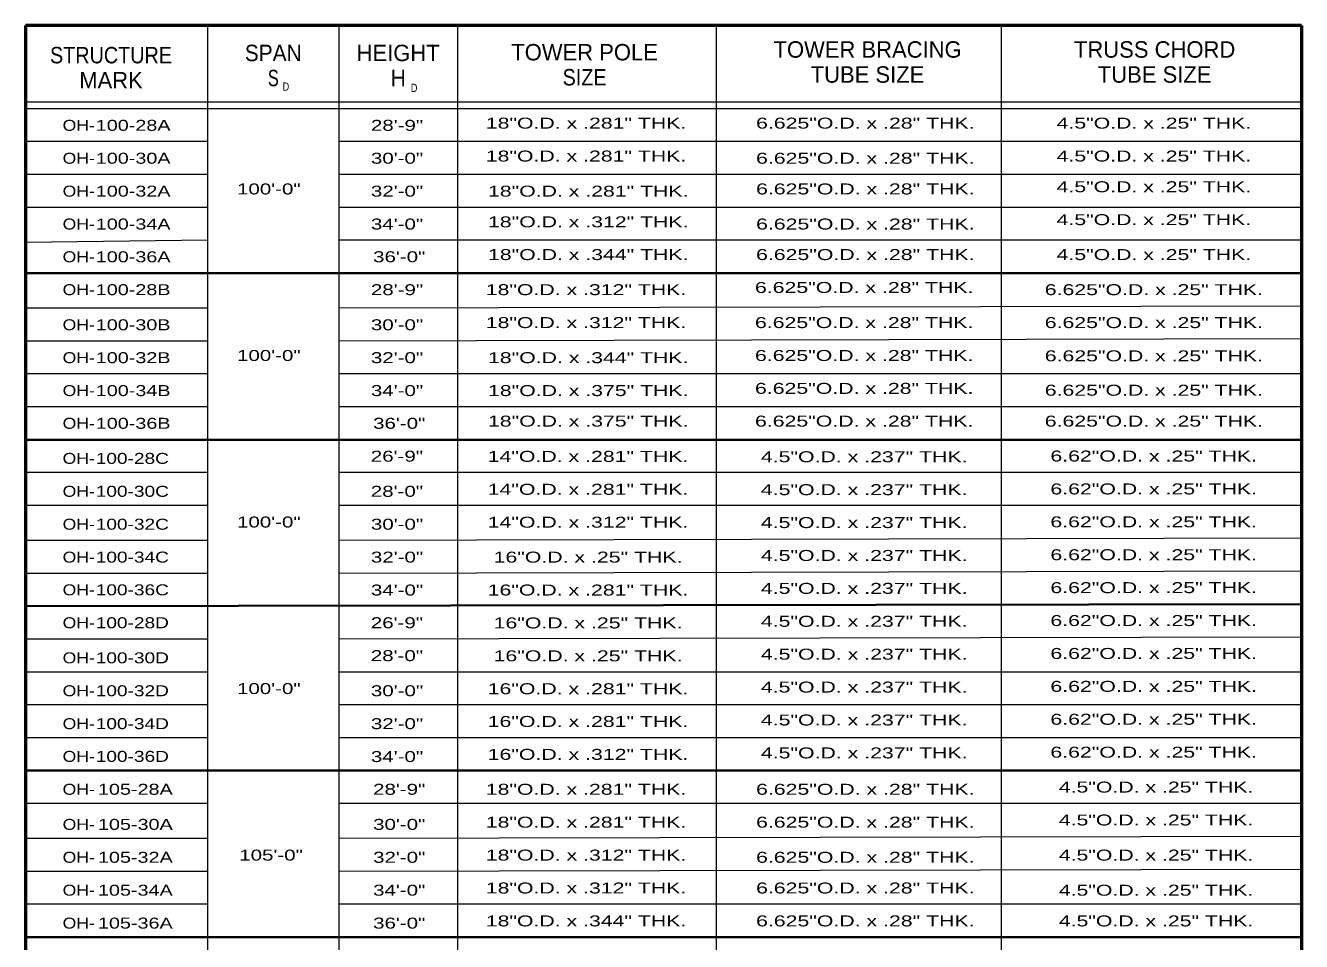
# Model space of a CAD drawing. Extents: x -34822.8 to -34815.8, y -181502.4 to -181492.3.
# Drawn here: x -34822.76 to -34815.78, y -181497.35 to -181492.34 of the extents above; entities that cross this region are included whole.
import ezdxf
from ezdxf.enums import TextEntityAlignment as Align

# ---------------------------------------------------------------- set-up
doc = ezdxf.new("R2010")
doc.units = 0
doc.header["$LTSCALE"] = 0.024
doc.layers.add('1', color=7, linetype='Continuous', lineweight=13)
doc.layers.add('13', color=7, linetype='Continuous')

msp = doc.modelspace()

# ---------------------------------------------------------------- linework, layer by layer
at = {"layer": '1', "lineweight": 53}
for p, q in [((-34815.779, -181492.336), (-34822.756, -181492.336)), ((-34822.756, -181492.336), (-34822.756, -181500.045)), ((-34815.779, -181492.336), (-34815.779, -181500.033))]:
    msp.add_line(p, q, dxfattribs=at)
at = {"layer": '1'}
for p, q in [((-34821.761, -181492.336), (-34821.761, -181500.045)), ((-34821.042, -181492.336), (-34821.042, -181500.045)), ((-34820.394, -181492.336), (-34820.394, -181500.045)), ((-34818.98, -181492.336), (-34818.98, -181500.045)), ((-34817.421, -181492.336), (-34817.421, -181500.045)), ((-34815.779, -181492.756), (-34822.756, -181492.756)), ((-34815.779, -181492.792), (-34822.756, -181492.792)), ((-34821.761, -181492.971), (-34822.756, -181492.971)), ((-34815.779, -181492.971), (-34821.042, -181492.971)), ((-34821.761, -181493.151), (-34822.756, -181493.151)), ((-34815.779, -181493.151), (-34821.042, -181493.151)), ((-34821.761, -181493.331), (-34822.756, -181493.331)), ((-34815.779, -181493.331), (-34821.042, -181493.331)), ((-34821.761, -181493.511), (-34822.756, -181493.523)), ((-34815.779, -181493.511), (-34821.042, -181493.511)), ((-34821.761, -181493.883), (-34822.756, -181493.883)), ((-34815.779, -181493.871), (-34821.042, -181493.883)), ((-34821.761, -181494.062), (-34822.756, -181494.062)), ((-34815.779, -181494.05), (-34821.042, -181494.062)), ((-34821.761, -181494.242), (-34822.756, -181494.242)), ((-34815.779, -181494.242), (-34821.042, -181494.242)), ((-34821.761, -181494.422), (-34822.756, -181494.422)), ((-34815.779, -181494.422), (-34821.042, -181494.422)), ((-34821.761, -181494.782), (-34822.756, -181494.782)), ((-34815.779, -181494.782), (-34821.042, -181494.782)), ((-34821.761, -181494.962), (-34822.756, -181494.962)), ((-34815.779, -181494.962), (-34821.042, -181494.962)), ((-34815.779, -181495.141), (-34821.042, -181495.153)), ((-34821.761, -181495.153), (-34822.756, -181495.153)), ((-34821.761, -181495.333), (-34822.756, -181495.333)), ((-34815.779, -181495.321), (-34821.042, -181495.333)), ((-34821.761, -181495.693), (-34822.756, -181495.693)), ((-34815.779, -181495.681), (-34821.042, -181495.693)), ((-34821.761, -181495.873), (-34822.756, -181495.873)), ((-34815.779, -181495.873), (-34821.042, -181495.873)), ((-34821.761, -181496.052), (-34822.756, -181496.052)), ((-34815.779, -181496.052), (-34821.042, -181496.052)), ((-34821.761, -181496.232), (-34822.756, -181496.232)), ((-34815.779, -181496.232), (-34821.042, -181496.232)), ((-34821.761, -181496.592), (-34822.756, -181496.592)), ((-34815.779, -181496.592), (-34821.042, -181496.592)), ((-34821.761, -181496.784), (-34822.756, -181496.784)), ((-34815.779, -181496.772), (-34821.042, -181496.784)), ((-34815.779, -181496.952), (-34821.042, -181496.964)), ((-34821.761, -181496.964), (-34822.756, -181496.964)), ((-34821.761, -181497.143), (-34822.756, -181497.143)), ((-34815.779, -181497.143), (-34821.042, -181497.143))]:
    msp.add_line(p, q, dxfattribs=at)
at = {"layer": '1', "lineweight": 35}
for p, q in [((-34815.779, -181493.691), (-34822.756, -181493.691)), ((-34815.779, -181494.602), (-34822.756, -181494.602)), ((-34815.779, -181495.501), (-34822.756, -181495.513)), ((-34815.779, -181496.412), (-34822.756, -181496.412)), ((-34815.779, -181497.323), (-34822.756, -181497.323))]:
    msp.add_line(p, q, dxfattribs=at)

# ---------------------------------------------------------------- texts
at = {"layer": '13'}
for s, height, p in [('TOWER BRACING', 0.08991, (-34818.1515, -181492.512)), ('TRUSS CHORD', 0.09, (-34816.582, -181492.512)), ('HEIGHT', 0.08991, (-34820.7185, -181492.531)), ('TOWER POLE', 0.08991, (-34819.699, -181492.527)), ('TUBE SIZE', 0.08991, (-34818.152, -181492.649)), ('TUBE SIZE', 0.09, (-34816.582, -181492.649)), ('MARK', 0.08991, (-34822.2885, -181492.68))]:
    msp.add_text(s, height=height, dxfattribs=at).set_placement(p, align=Align.CENTER)
for s, height, width, p in [('STRUCTURE', 0.08991, 0.9, (-34822.2885, -181492.543)), ('SPAN', 0.08991, 0.95, (-34821.4015, -181492.531)), ('S', 0.0899, 0.75, (-34821.401, -181492.668)), ('H', 0.0899, 0.95, (-34820.7175, -181492.668)), ('SIZE', 0.08991, 0.9, (-34819.699, -181492.664)), ('D', 0.0455, 0.8, (-34821.332, -181492.693)), ('D', 0.0455, 0.8, (-34820.631, -181492.7)), ('18"O.D. x .281" THK.', 0.05992, 1.45, (-34819.691, -181492.9)), ('6.625"O.D. x .28" THK.', 0.06, 1.45, (-34818.164, -181492.9)), ('4.5"O.D. x .25" THK.', 0.05992, 1.45, (-34816.586, -181492.9)), ('OH-', 0.05992, 1.2, (-34822.465, -181492.912)), ('28\'-9"', 0.05992, 1.4, (-34820.7245, -181492.912)), ('OH-', 0.05992, 1.2, (-34822.465, -181493.092)), ('30\'-0"', 0.05992, 1.4, (-34820.7245, -181493.092)), ('18"O.D. x .281" THK.', 0.05992, 1.45, (-34819.691, -181493.08)), ('6.625"O.D. x .28" THK.', 0.06, 1.45, (-34818.164, -181493.092)), ('4.5"O.D. x .25" THK.', 0.05992, 1.45, (-34816.586, -181493.08)), ('4.5"O.D. x .25" THK.', 0.05992, 1.45, (-34816.586, -181493.248)), ('OH-', 0.05992, 1.2, (-34822.465, -181493.272)), ('100\'-0"', 0.05992, 1.4, (-34821.4255, -181493.26)), ('32\'-0"', 0.05992, 1.4, (-34820.7245, -181493.272)), ('18"O.D. x .281" THK.', 0.05992, 1.45, (-34819.679, -181493.272)), ('6.625"O.D. x .28" THK.', 0.06, 1.45, (-34818.164, -181493.26)), ('OH-', 0.05992, 1.2, (-34822.465, -181493.452)), ('34\'-0"', 0.05992, 1.4, (-34820.7245, -181493.452)), ('18"O.D. x .312" THK.', 0.05992, 1.45, (-34819.679, -181493.44)), ('6.625"O.D. x .28" THK.', 0.06, 1.45, (-34818.164, -181493.452)), ('4.5"O.D. x .25" THK.', 0.05992, 1.45, (-34816.586, -181493.428)), ('OH-', 0.05992, 1.2, (-34822.465, -181493.631)), ('36\'-0"', 0.05992, 1.4, (-34820.7125, -181493.631)), ('18"O.D. x .344" THK.', 0.05992, 1.45, (-34819.679, -181493.619)), ('6.625"O.D. x .28" THK.', 0.06, 1.45, (-34818.164, -181493.619)), ('4.5"O.D. x .25" THK.', 0.05992, 1.45, (-34816.586, -181493.619)), ('6.625"O.D. x .28" THK.', 0.06, 1.45, (-34818.17, -181493.799)), ('OH-', 0.05992, 1.2, (-34822.465, -181493.811)), ('28\'-9"', 0.05992, 1.4, (-34820.7245, -181493.811)), ('18"O.D. x .312" THK.', 0.05992, 1.45, (-34819.691, -181493.811)), ('6.625"O.D. x .25" THK.', 0.05992, 1.45, (-34816.586, -181493.811)), ('OH-', 0.05992, 1.2, (-34822.465, -181494.003)), ('30\'-0"', 0.05992, 1.4, (-34820.7245, -181494.003)), ('18"O.D. x .312" THK.', 0.05992, 1.45, (-34819.691, -181493.991)), ('6.625"O.D. x .28" THK.', 0.06, 1.45, (-34818.17, -181493.991)), ('6.625"O.D. x .25" THK.', 0.05992, 1.45, (-34816.586, -181493.991)), ('OH-', 0.05992, 1.2, (-34822.465, -181494.183)), ('100\'-0"', 0.05992, 1.4, (-34821.4255, -181494.171)), ('32\'-0"', 0.05992, 1.4, (-34820.7245, -181494.183)), ('18"O.D. x .344" THK.', 0.05992, 1.45, (-34819.679, -181494.183)), ('6.625"O.D. x .28" THK.', 0.06, 1.45, (-34818.17, -181494.171)), ('6.625"O.D. x .25" THK.', 0.05992, 1.45, (-34816.586, -181494.173)), ('OH-', 0.05992, 1.2, (-34822.465, -181494.363)), ('34\'-0"', 0.05992, 1.4, (-34820.7245, -181494.363)), ('18"O.D. x .375" THK.', 0.05992, 1.45, (-34819.679, -181494.363)), ('6.625"O.D. x .28" THK.', 0.06, 1.45, (-34818.17, -181494.351)), ('6.625"O.D. x .25" THK.', 0.05992, 1.45, (-34816.586, -181494.361)), ('OH-', 0.05992, 1.2, (-34822.465, -181494.542)), ('36\'-0"', 0.05992, 1.4, (-34820.7125, -181494.542)), ('18"O.D. x .375" THK.', 0.05992, 1.45, (-34819.679, -181494.53)), ('18"O.D. x .375" THK.', 0.05992, 1.45, (-34819.679, -181494.53)), ('18"O.D. x .375" THK.', 0.05992, 1.45, (-34819.679, -181494.53)), ('18"O.D. x .375" THK.', 0.05992, 1.45, (-34819.679, -181494.53)), ('6.625"O.D. x .28" THK.', 0.06, 1.45, (-34818.17, -181494.53)), ('6.625"O.D. x .25" THK.', 0.05992, 1.45, (-34816.586, -181494.53)), ('OH-', 0.05992, 1.2, (-34822.465, -181494.734)), ('26\'-9"', 0.06, 1.4, (-34820.725, -181494.722)), ('14"O.D. x .281" THK.', 0.06, 1.45, (-34819.68, -181494.723)), ('4.5"O.D. x .237" THK.', 0.06, 1.45, (-34818.17, -181494.725)), ('6.62"O.D. x .25" THK.', 0.06, 1.45, (-34816.587, -181494.721)), ('OH-', 0.05992, 1.2, (-34822.465, -181494.914)), ('28\'-0"', 0.06, 1.4, (-34820.725, -181494.914)), ('14"O.D. x .281" THK.', 0.06, 1.45, (-34819.68, -181494.903)), ('4.5"O.D. x .237" THK.', 0.06, 1.45, (-34818.17, -181494.905)), ('6.62"O.D. x .25" THK.', 0.06, 1.45, (-34816.587, -181494.901)), ('OH-', 0.05992, 1.2, (-34822.465, -181495.094)), ('100\'-0"', 0.05992, 1.4, (-34821.4255, -181495.082)), ('30\'-0"', 0.05992, 1.4, (-34820.7245, -181495.094)), ('14"O.D. x .312" THK.', 0.06, 1.45, (-34819.68, -181495.083)), ('4.5"O.D. x .237" THK.', 0.06, 1.45, (-34818.17, -181495.085)), ('6.62"O.D. x .25" THK.', 0.06, 1.45, (-34816.587, -181495.081)), ('4.5"O.D. x .237" THK.', 0.06, 1.45, (-34818.17, -181495.265)), ('6.62"O.D. x .25" THK.', 0.06, 1.45, (-34816.587, -181495.261)), ('OH-', 0.05992, 1.2, (-34822.465, -181495.274)), ('32\'-0"', 0.05992, 1.4, (-34820.7245, -181495.274)), ('16"O.D. x .25" THK.', 0.06, 1.45, (-34819.68, -181495.274)), ('OH-', 0.05992, 1.2, (-34822.465, -181495.453)), ('34\'-0"', 0.05992, 1.4, (-34820.7245, -181495.454)), ('16"O.D. x .281" THK.', 0.06, 1.45, (-34819.68, -181495.454)), ('4.5"O.D. x .237" THK.', 0.06, 1.45, (-34818.17, -181495.445)), ('6.62"O.D. x .25" THK.', 0.06, 1.45, (-34816.587, -181495.441)), ('6.62"O.D. x .25" THK.', 0.06, 1.45, (-34816.587, -181495.621)), ('OH-', 0.05992, 1.2, (-34822.465, -181495.633)), ('26\'-9"', 0.06, 1.4, (-34820.725, -181495.633)), ('16"O.D. x .25" THK.', 0.06, 1.45, (-34819.68, -181495.634)), ('4.5"O.D. x .237" THK.', 0.06, 1.45, (-34818.17, -181495.625)), ('OH-', 0.05992, 1.2, (-34822.465, -181495.825)), ('28\'-0"', 0.06, 1.4, (-34820.725, -181495.813)), ('16"O.D. x .25" THK.', 0.06, 1.45, (-34819.68, -181495.814)), ('4.5"O.D. x .237" THK.', 0.06, 1.45, (-34818.17, -181495.805)), ('6.62"O.D. x .25" THK.', 0.06, 1.45, (-34816.587, -181495.801)), ('OH-', 0.05992, 1.2, (-34822.465, -181496.005)), ('100\'-0"', 0.05992, 1.4, (-34821.4255, -181495.993)), ('30\'-0"', 0.05992, 1.4, (-34820.7245, -181496.005)), ('16"O.D. x .281" THK.', 0.06, 1.45, (-34819.68, -181495.994)), ('4.5"O.D. x .237" THK.', 0.06, 1.45, (-34818.17, -181495.985)), ('6.62"O.D. x .25" THK.', 0.06, 1.45, (-34816.587, -181495.981)), ('16"O.D. x .281" THK.', 0.06, 1.45, (-34819.68, -181496.173)), ('4.5"O.D. x .237" THK.', 0.06, 1.45, (-34818.17, -181496.165)), ('6.62"O.D. x .25" THK.', 0.06, 1.45, (-34816.587, -181496.161)), ('OH-', 0.05992, 1.2, (-34822.465, -181496.185)), ('32\'-0"', 0.05992, 1.4, (-34820.7245, -181496.185)), ('OH-', 0.05992, 1.2, (-34822.465, -181496.364)), ('34\'-0"', 0.05992, 1.4, (-34820.7245, -181496.365)), ('16"O.D. x .312" THK.', 0.06, 1.45, (-34819.68, -181496.353)), ('4.5"O.D. x .237" THK.', 0.06, 1.45, (-34818.17, -181496.345)), ('6.62"O.D. x .25" THK.', 0.06, 1.45, (-34816.587, -181496.341)), ('OH-', 0.05992, 1.2, (-34822.465, -181496.544)), ('28\'-9"', 0.05992, 1.4, (-34820.7125, -181496.544)), ('18"O.D. x .281" THK.', 0.05992, 1.45, (-34819.691, -181496.544)), ('6.625"O.D. x .28" THK.', 0.06, 1.45, (-34818.164, -181496.544)), ('4.5"O.D. x .25" THK.', 0.05992, 1.45, (-34816.574, -181496.532)), ('OH-', 0.05992, 1.2, (-34822.465, -181496.736)), ('30\'-0"', 0.05992, 1.4, (-34820.7125, -181496.736)), ('18"O.D. x .281" THK.', 0.05992, 1.45, (-34819.691, -181496.724)), ('6.625"O.D. x .28" THK.', 0.06, 1.45, (-34818.164, -181496.724)), ('4.5"O.D. x .25" THK.', 0.05992, 1.45, (-34816.574, -181496.712)), ('OH-', 0.05992, 1.2, (-34822.465, -181496.916)), ('105\'-0"', 0.05992, 1.4, (-34821.4135, -181496.904)), ('32\'-0"', 0.05992, 1.4, (-34820.7125, -181496.916)), ('18"O.D. x .312" THK.', 0.05992, 1.45, (-34819.691, -181496.904)), ('6.625"O.D. x .28" THK.', 0.06, 1.45, (-34818.164, -181496.916)), ('4.5"O.D. x .25" THK.', 0.05992, 1.45, (-34816.574, -181496.904)), ('18"O.D. x .312" THK.', 0.05992, 1.45, (-34819.691, -181497.084)), ('6.625"O.D. x .28" THK.', 0.06, 1.45, (-34818.164, -181497.084)), ('OH-', 0.05992, 1.2, (-34822.465, -181497.096)), ('34\'-0"', 0.05992, 1.4, (-34820.7125, -181497.096)), ('4.5"O.D. x .25" THK.', 0.05992, 1.45, (-34816.574, -181497.096)), ('OH-', 0.05992, 1.2, (-34822.465, -181497.276)), ('36\'-0"', 0.05992, 1.4, (-34820.7125, -181497.276)), ('18"O.D. x .344" THK.', 0.05992, 1.45, (-34819.691, -181497.264)), ('6.625"O.D. x .28" THK.', 0.06, 1.45, (-34818.164, -181497.264)), ('4.5"O.D. x .25" THK.', 0.05992, 1.45, (-34816.574, -181497.264))]:
    msp.add_text(s, height=height, dxfattribs=dict(at, width=width)).set_placement(p, align=Align.CENTER)
for s, height, width, p in [('100-28A', 0.05992, 1.35, (-34822.372, -181492.912)), ('100-30A', 0.05992, 1.35, (-34822.372, -181493.092)), ('100-32A', 0.05992, 1.35, (-34822.372, -181493.272)), ('100-34A', 0.05992, 1.35, (-34822.372, -181493.452)), ('100-36A', 0.05992, 1.35, (-34822.372, -181493.631)), ('100-28B', 0.05992, 1.35, (-34822.372, -181493.811)), ('100-30B', 0.05992, 1.35, (-34822.372, -181494.003)), ('100-32B', 0.05992, 1.35, (-34822.372, -181494.183)), ('100-34B', 0.05992, 1.35, (-34822.372, -181494.363)), ('100-36B', 0.05992, 1.35, (-34822.372, -181494.542)), ('100-28C', 0.06, 1.3, (-34822.372, -181494.734)), ('100-30C', 0.06, 1.3, (-34822.372, -181494.914)), ('100-32C', 0.06, 1.3, (-34822.372, -181495.094)), ('100-34C', 0.06, 1.3, (-34822.372, -181495.274)), ('100-36C', 0.06, 1.3, (-34822.372, -181495.453)), ('100-28D', 0.06, 1.3, (-34822.372, -181495.633)), ('100-30D', 0.06, 1.3, (-34822.372, -181495.825)), ('100-32D', 0.06, 1.3, (-34822.372, -181496.005)), ('100-34D', 0.06, 1.3, (-34822.372, -181496.185)), ('100-36D', 0.06, 1.3, (-34822.372, -181496.364)), ('105-28A', 0.05992, 1.35, (-34822.36, -181496.544)), ('105-30A', 0.05992, 1.35, (-34822.36, -181496.736)), ('105-32A', 0.05992, 1.35, (-34822.36, -181496.916)), ('105-34A', 0.05992, 1.35, (-34822.36, -181497.096)), ('105-36A', 0.05992, 1.35, (-34822.36, -181497.276))]:
    msp.add_text(s, height=height, dxfattribs=dict(at, width=width)).set_placement(p)

doc.saveas('drawing.dxf')
